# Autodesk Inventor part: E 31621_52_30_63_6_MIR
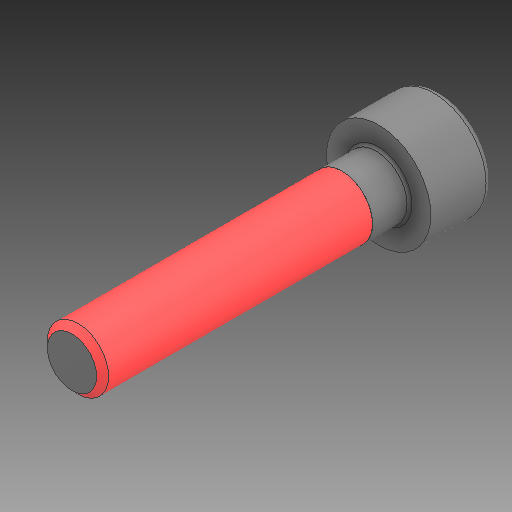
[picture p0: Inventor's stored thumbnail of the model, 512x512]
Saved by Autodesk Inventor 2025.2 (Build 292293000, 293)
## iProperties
Created: 2025-03
Part Number: E 31621_52_30_63_6_MIR
Material: Všeobecné
Document SubType Name: Modeling
Designer: Patrik
Stock Number: E 31621_52_30_63
Mass: 0.73741 g
Surface Area: 6.62537 cm^2
Volume: 0.73741 cm^3
Density: 1 g/cm^3
Appearance: Výchozí
Author: Patrik
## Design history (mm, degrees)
derived "E 31621_52_30_63_6.ipt"
feature "Těleso1::E 31621_52_30_63_6.ipt" dims "d0" = 10
tag "Prvek štítků1"
node "Těleso1"
